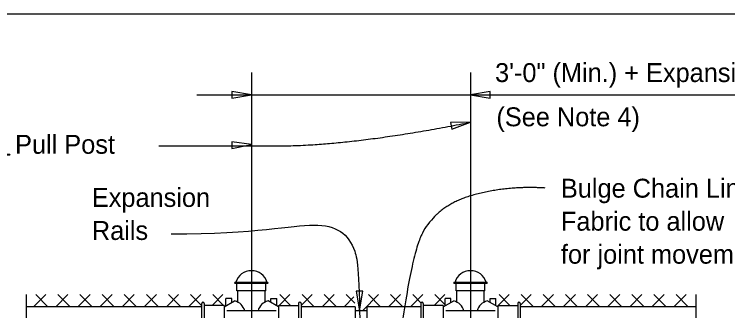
# Model space of a CAD drawing. Extents: x 110698 to 110915, y 110390 to 110472.
# Drawn here: x 110797.65 to 110805.25, y 110461.64 to 110464.8 of the extents above; entities that cross this region are included whole.
import ezdxf

# ---------------------------------------------------------------- set-up
doc = ezdxf.new("R2010")
doc.units = 0
for name, color, linetype in [('ActivePts-ConstElements', 7, 'Continuous'), ('AdhocPoint_dp', 7, 'Continuous'), ('Border', 7, 'Continuous'), ('PlotBorder_dp', 7, 'Continuous'), ('SheetBorder_dp', 7, 'Continuous'), ('TextMisc', 7, 'Continuous')]:
    doc.layers.add(name, color=color, linetype=linetype)

msp = doc.modelspace()

# ---------------------------------------------------------------- linework, layer by layer
at = {"layer": 'ActivePts-ConstElements'}
msp.add_lwpolyline([(110774.0658, 110438.856), (110815.1163, 110438.856), (110815.1163, 110464.8021), (110774.0658, 110464.8021)], close=True, dxfattribs=at)
at = {"layer": 'AdhocPoint_dp'}
for p, q in [((110800.1776, 110464.1815), (110800.1776, 110451.4891)), ((110802.5109, 110464.1815), (110802.5109, 110452.6217))]:
    msp.add_line(p, q, dxfattribs=at)
at = {"layer": 'PlotBorder_dp'}
msp.add_line((110799.5955, 110463.9443), (110808.4984, 110463.9443), dxfattribs=at)
for points in [[(110800.1776, 110463.9443), (110799.9693, 110463.9796), (110799.9693, 110463.909)], [(110802.5109, 110463.9443), (110802.7192, 110463.909), (110802.7192, 110463.9796)], [(110802.5109, 110463.6509), (110802.2997, 110463.6474), (110802.3127, 110463.578)], [(110800.1776, 110463.4142), (110799.9683, 110463.4431), (110799.9705, 110463.3726)], [(110801.3305, 110461.6414), (110801.3658, 110461.8497), (110801.2952, 110461.8497)]]:
    msp.add_lwpolyline(points, close=True, dxfattribs=at)
for points in [[(110797.7778, 110461.8153), (110797.7778, 110459.8591), (110797.8811, 110459.8591), (110797.7778, 110459.8141), (110797.6745, 110459.7691), (110797.7778, 110459.7691), (110797.7778, 110458.8754)], [(110804.9109, 110461.8153), (110804.9109, 110459.8591), (110805.0142, 110459.8591), (110804.9109, 110459.8141), (110804.8075, 110459.7691), (110804.9109, 110459.7691), (110804.9109, 110458.8754)]]:
    msp.add_lwpolyline(points, dxfattribs=at)
for points, degree in [([(110799.1935, 110463.3986), (110799.6472, 110463.3986), (110801.2435, 110463.3986), (110802.5109, 110463.6509)], 2), ([(110803.3059, 110462.9496), (110802.8774, 110462.9749), (110802.1464, 110462.7562), (110801.8439, 110462.1675), (110801.6758, 110460.6605)], 2), ([(110799.323, 110462.4611), (110800.2477, 110462.4611), (110800.9526, 110462.6491), (110801.3431, 110462.3679), (110801.3442, 110461.8077), (110801.3442, 110456.2247)], 3)]:
    msp.add_open_spline(points, degree=degree, dxfattribs=at)
at = {"layer": 'SheetBorder_dp'}
for p, q in [((110797.9884, 110461.8133), (110797.8582, 110461.6831)), ((110798.0111, 110461.6831), (110797.881, 110461.8133)), ((110798.2241, 110461.8133), (110798.0939, 110461.6831)), ((110798.2468, 110461.6831), (110798.1167, 110461.8133)), ((110798.4598, 110461.8133), (110798.3296, 110461.6831)), ((110798.4825, 110461.6831), (110798.3524, 110461.8133)), ((110798.6955, 110461.8133), (110798.5653, 110461.6831)), ((110798.7182, 110461.6831), (110798.5881, 110461.8133)), ((110798.9312, 110461.8133), (110798.801, 110461.6831)), ((110798.9539, 110461.6831), (110798.8238, 110461.8133)), ((110799.1669, 110461.8133), (110799.0368, 110461.6831)), ((110799.1896, 110461.6831), (110799.0595, 110461.8133)), ((110799.4026, 110461.8133), (110799.2725, 110461.6831)), ((110799.4253, 110461.6831), (110799.2952, 110461.8133)), ((110799.6383, 110461.8133), (110799.5082, 110461.6831)), ((110799.6482, 110461.6959), (110799.5309, 110461.8133)), ((110799.874, 110461.8133), (110799.7593, 110461.6985)), ((110799.8813, 110461.6985), (110799.7666, 110461.8133)), ((110800.4738, 110461.6985), (110800.5886, 110461.8133)), ((110800.4811, 110461.8133), (110800.5959, 110461.6985)), ((110800.7069, 110461.6959), (110800.8243, 110461.8133)), ((110800.7168, 110461.8133), (110800.847, 110461.6831)), ((110800.9298, 110461.6831), (110801.06, 110461.8133)), ((110800.9525, 110461.8133), (110801.0827, 110461.6831)), ((110801.1655, 110461.6831), (110801.2703, 110461.7879)), ((110801.1882, 110461.8133), (110801.2803, 110461.7211)), ((110801.3595, 110461.6414), (110801.5314, 110461.8133)), ((110801.4239, 110461.8133), (110801.5541, 110461.6831)), ((110801.6369, 110461.6831), (110801.7671, 110461.8133)), ((110801.6596, 110461.8133), (110801.7898, 110461.6831)), ((110801.8726, 110461.6831), (110802.0028, 110461.8133)), ((110801.8953, 110461.8133), (110801.9815, 110461.7271)), ((110802.1237, 110461.6985), (110802.2385, 110461.8133)), ((110802.131, 110461.8133), (110802.24, 110461.7043)), ((110802.8072, 110461.6985), (110802.9219, 110461.8133)), ((110802.8145, 110461.8133), (110802.9292, 110461.6985)), ((110803.0402, 110461.6959), (110803.1576, 110461.8133)), ((110803.0502, 110461.8133), (110803.1803, 110461.6831)), ((110803.2631, 110461.6831), (110803.3933, 110461.8133)), ((110803.2859, 110461.8133), (110803.416, 110461.6831)), ((110803.4988, 110461.6831), (110803.629, 110461.8133)), ((110803.5216, 110461.8133), (110803.6517, 110461.6831)), ((110803.7345, 110461.6831), (110803.8647, 110461.8133)), ((110803.7573, 110461.8133), (110803.8874, 110461.6831)), ((110803.9702, 110461.6831), (110804.1004, 110461.8133)), ((110803.993, 110461.8133), (110804.1231, 110461.6831)), ((110804.2059, 110461.6831), (110804.3361, 110461.8133)), ((110804.2287, 110461.8133), (110804.3588, 110461.6831)), ((110804.4416, 110461.6831), (110804.5718, 110461.8133)), ((110804.4644, 110461.8133), (110804.5945, 110461.6831)), ((110804.6773, 110461.6831), (110804.8075, 110461.8133)), ((110804.7001, 110461.8133), (110804.8302, 110461.6831))]:
    msp.add_line(p, q, dxfattribs=at)
at = {"layer": 'TextMisc'}
for p, q in [((110800.0053, 110461.9452), (110800.3499, 110461.9452)), ((110802.3386, 110461.9452), (110802.6832, 110461.9452)), ((110800.3499, 110461.933), (110800.0053, 110461.933)), ((110800.0235, 110461.8532), (110800.0235, 110461.933)), ((110800.3316, 110461.8532), (110800.3316, 110461.933)), ((110802.6832, 110461.933), (110802.3386, 110461.933)), ((110802.3568, 110461.8532), (110802.3568, 110461.933)), ((110802.665, 110461.8532), (110802.665, 110461.933)), ((110800.3316, 110461.8532), (110800.0235, 110461.8532)), ((110800.0318, 110461.7333), (110800.0318, 110461.8532)), ((110800.3234, 110461.7333), (110800.3234, 110461.8532)), ((110802.665, 110461.8532), (110802.3568, 110461.8532)), ((110802.3651, 110461.7333), (110802.3651, 110461.8532)), ((110802.6568, 110461.7333), (110802.6568, 110461.8532)), ((110799.6482, 110461.7181), (110799.6482, 110461.4084)), ((110799.675, 110461.7181), (110799.675, 110461.4084)), ((110799.888, 110461.6838), (110799.9988, 110461.7452)), ((110799.9067, 110461.6941), (110799.9067, 110461.7716)), ((110799.9692, 110461.7716), (110799.9067, 110461.7716)), ((110799.9692, 110461.7287), (110799.9692, 110461.7716)), ((110800.4671, 110461.6838), (110800.3563, 110461.7452)), ((110800.3859, 110461.7299), (110800.3859, 110461.7716)), ((110800.3859, 110461.7716), (110800.4484, 110461.7716)), ((110800.4484, 110461.6941), (110800.4484, 110461.7716)), ((110800.6801, 110461.7181), (110800.6801, 110461.4084)), ((110800.7069, 110461.7181), (110800.7069, 110461.4084)), ((110801.9815, 110461.7181), (110801.9815, 110461.4084)), ((110802.0084, 110461.7181), (110802.0084, 110461.4084)), ((110802.2213, 110461.6838), (110802.3322, 110461.7452)), ((110802.24, 110461.6941), (110802.24, 110461.7716)), ((110802.3025, 110461.7716), (110802.24, 110461.7716)), ((110802.3025, 110461.7287), (110802.3025, 110461.7716)), ((110802.8004, 110461.6838), (110802.6896, 110461.7452)), ((110802.7193, 110461.7299), (110802.7193, 110461.7716)), ((110802.7193, 110461.7716), (110802.7818, 110461.7716)), ((110802.7818, 110461.6941), (110802.7818, 110461.7716)), ((110803.0134, 110461.7181), (110803.0134, 110461.4084)), ((110803.0402, 110461.7181), (110803.0402, 110461.4084)), ((110799.6482, 110461.6831), (110797.7777, 110461.6831)), ((110799.888, 110461.6985), (110799.675, 110461.6985)), ((110799.888, 110461.6985), (110799.888, 110461.4263)), ((110800.4399, 110461.6412), (110799.9151, 110461.6412)), ((110800.4671, 110461.6985), (110800.4671, 110461.4263)), ((110800.4671, 110461.6985), (110800.6801, 110461.6985)), ((110801.2817, 110461.6831), (110800.7069, 110461.6831)), ((110801.2817, 110461.6831), (110801.2817, 110461.4435)), ((110801.4067, 110461.6414), (110801.2817, 110461.6414)), ((110801.4067, 110461.6831), (110801.4067, 110461.4435)), ((110801.9815, 110461.6831), (110801.4067, 110461.6831)), ((110802.2213, 110461.6985), (110802.0084, 110461.6985)), ((110802.2213, 110461.6985), (110802.2213, 110461.4263)), ((110802.7733, 110461.6412), (110802.2485, 110461.6412)), ((110802.8004, 110461.6985), (110802.8004, 110461.4263)), ((110802.8004, 110461.6985), (110803.0134, 110461.6985)), ((110804.9108, 110461.6831), (110803.0402, 110461.6831))]:
    msp.add_line(p, q, dxfattribs=at)
for centre, radius, start, end in [((110800.0054, 110461.9389), 0.00613, 91.1647, 268.8353), ((110800.3497, 110461.9389), 0.00613, 271.1647, 88.8353), ((110802.3388, 110461.9389), 0.00613, 91.1647, 268.8353), ((110802.6831, 110461.9389), 0.00613, 271.1647, 88.8353), ((110799.6617, 110461.718), 0.0134, 0, 180), ((110800.6934, 110461.718), 0.0134, 0, 180), ((110801.9951, 110461.718), 0.0134, 0, 180), ((110803.0267, 110461.718), 0.0134, 0, 180)]:
    msp.add_arc(centre, radius, start, end, dxfattribs=at)
for centre, major_axis, start_param, end_param in [((110800.1783, 110461.9042), (0.1711, 0), 0.252602, 2.888574), ((110802.5116, 110461.9042), (0.1711, 0), 0.252602, 2.888574), ((110799.9644, 110461.6092), (0.146, 0), 0.231126, 1.331255), ((110800.3908, 110461.6092), (-0.146, 0), 4.95193, 6.05206), ((110802.2977, 110461.6092), (0.146, 0), 0.231126, 1.331255), ((110802.7241, 110461.6092), (-0.146, 0), 4.95193, 6.05206)]:
    msp.add_ellipse(centre, major_axis=major_axis, ratio=0.957868, start_param=start_param, end_param=end_param, dxfattribs=at)

# ---------------------------------------------------------------- texts
at = {"layer": 'Border'}
for s, p in [('3\'-0" (Min.) + Expansion Joint Opening', (110802.7726, 110464.0794)), ('(See Note 4)', (110802.7869, 110463.6077)), ('℄ Pull Post', (110797.4771, 110463.3149))]:
    msp.add_text(s, height=0.2016, dxfattribs=at).set_placement(p)
at = {"layer": 'PlotBorder_dp'}
for s, p in [('Bulge Chain Link ', (110803.4739, 110462.8469)), ('Expansion', (110798.4789, 110462.7481)), ('Fabric to allow ', (110803.4739, 110462.4949)), ('Rails', (110798.4789, 110462.3961)), ('for joint movement', (110803.4739, 110462.1429))]:
    msp.add_text(s, height=0.2016, dxfattribs=at).set_placement(p)

doc.saveas('drawing.dxf')
